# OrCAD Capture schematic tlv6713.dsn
size A
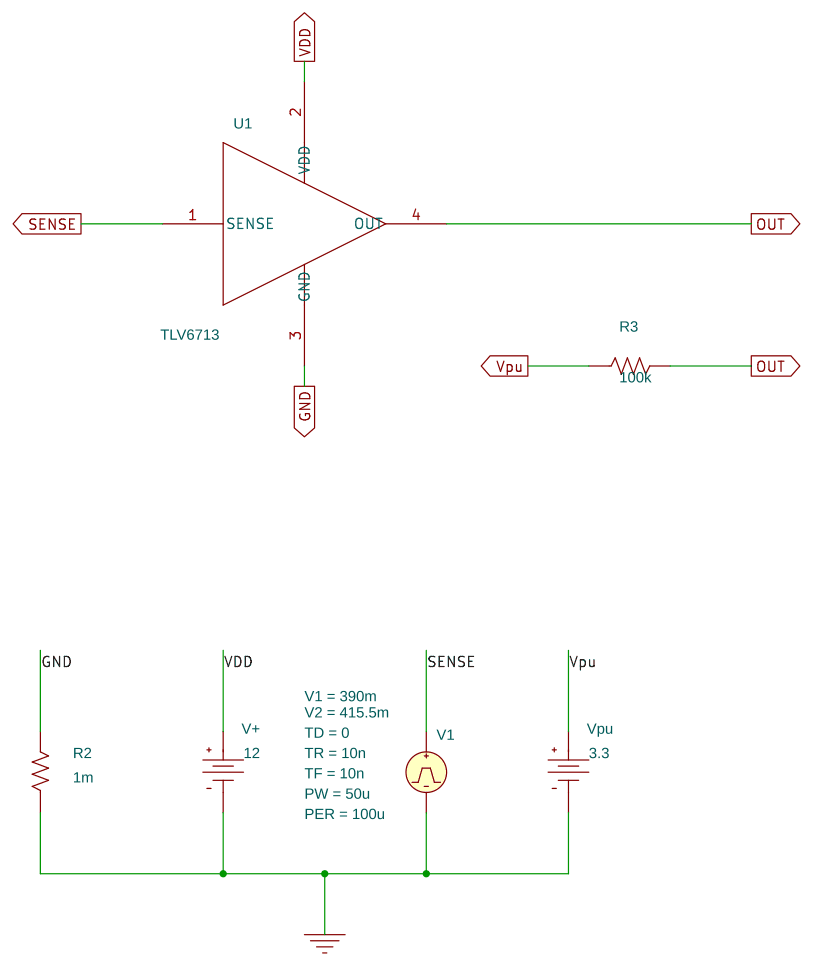
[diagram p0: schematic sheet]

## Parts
R2  1m  [AXRC05]
R3  100k  [AXRC05]
U1  TLV6713
V1  VPULSE
V+  VDC
Vpu  VDC

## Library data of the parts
R2 R3 = R
U1 = TLV6713
V1 = VPULSE: PER: 100u; PW: 50u; TD: 0; TF: 10n; TR: 10n; V1: 390m; V2: 415.5m
V+ = VDC: DC: 12
Vpu = VDC: DC: 3.3

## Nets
GND: R2.2 U1.3(GND)
VDD: U1.2(VDD) V+.0(+)
0: R2.1 V1.2(-) V+.1(-) Vpu.1(-)
OUT: R3.2 U1.4(OUT)
SENSE: U1.1(SENSE) V1.1(+)
Vpu: R3.1 Vpu.0(+)
